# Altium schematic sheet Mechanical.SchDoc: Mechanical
size A4; Date: Not used; ApprovedBy: Not used; CheckedBy: Not used; Author: Not used; CompanyName: STMicroelectronics; DrawnBy: Not used; Engineer: Not used; Organization: Not used; Address1: Not used; Address2: Not used; Address3: Not used; Address4: Not used; DocumentNumber: 8; Revision: Not used; SheetNumber: 8; SheetTotal: 8
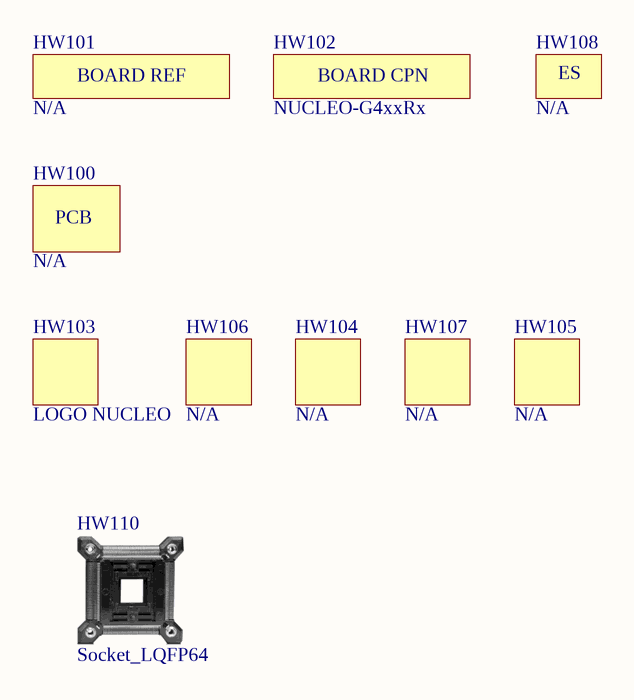
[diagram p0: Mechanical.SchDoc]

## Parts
HW100  (no value)  (no BOM)
HW101  (no value)  [STICKER_25X9]  (mechanical)
HW102  value NUCLEO-G4xxRx  (no BOM)
HW103  value LOGO NUCLEO  [LOGO_NUCLEO]  (no BOM)
HW104  (no value)  [LOGO_CE]  (no BOM)
HW105  (no value)  [LOGO_ROHS]  (no BOM)
HW106  (no value)  [LOGO_ST]  (no BOM)
HW107  (no value)  [LOGO_MAIN_1]  (no BOM)
HW108  (no value)  (mechanical)
HW110  SOCKET_LQFP64  (mechanical)

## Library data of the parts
HW100 = MCD-00216: PCB, xxxx for PCB number, Y for PCB revision; Part_Type: Misc; Part_Preference: Forbidden; Provided_By: SUBCO; Component_Country_Of_Origin: Unknown; ID: 2653; ShowFields: YES
HW101 = MCD-00235: Sticker to mention board reference + serial number; Part_Type: Misc; Part_Preference: Recommended; Provided_By: SUBCO; Component_Country_Of_Origin: Unknown; ID: 2632; ShowFields: YES
HW102 = MCD-00549: Product sticker to mention product CPN + product FG; Part_Type: Mechanical; Provided_By: Subcon; Initial_Board_Reference: MB1319
HW103 = MCD-00636: NUCLEO logo footprint for PCB; Part_Type: Accessory; Part_Preference: Forbidden; Component_Country_Of_Origin: Unknown; ID: 3110; ShowFields: YES
HW104 = MCD-00626: CE logo footprint for PCB; Part_Type: Misc; Part_Preference: Forbidden; Component_Country_Of_Origin: Unknown; ID: 3116; ShowFields: YES
HW105 = MCD-00628: ROHS logo footprint for PCB; Part_Type: Misc; Part_Preference: Forbidden; Component_Country_Of_Origin: Unknown; ID: 3120; ShowFields: YES
HW106 = MCD-00625: STMicroelectronics logo footprint for PCB; Part_Type: Misc; Part_Preference: Forbidden; Component_Country_Of_Origin: Unknown; ID: 3117; ShowFields: YES
HW107 = MCD-00627: Hand ESD logo footprint for PCB; Part_Type: Misc; Part_Preference: Forbidden; Component_Country_Of_Origin: Unknown; ID: 3114; ShowFields: YES
HW108 = MCD-00234: Sticker to mention ES sample; Part_Type: Misc; Part_Preference: Recommended; Provided_By: SUBCO; Component_Country_Of_Origin: Unknown; ID: 2634; ShowFields: YES
HW110 = MCD-01253: Yamaichi socket for LQFP64, with positioning pins.; Part_Type: Socket_IC; Manufacturer_Part_Number: IC149-064-169-B5; Part_Preference: Forbidden; Provided_By: SUBCO; Component_Country_Of_Origin: Unknown; ID: 3244; ShowFields: YES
